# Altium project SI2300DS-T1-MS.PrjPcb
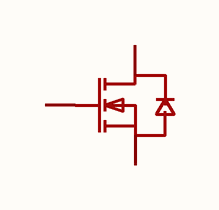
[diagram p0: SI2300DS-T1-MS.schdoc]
1 sheet, 1 parts. Net scope: global (net labels, ports and power ports of the same name join across sheets).

## Sheet SI2300DS-T1-MS.schdoc
size 127 x 101 mm

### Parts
Q?  si2300ds-t1-ms  [SOT-23-3_L2.9-W1.6-P1.90-LS2.8-BR]  (value not drawn)

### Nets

Not connected (* = marked no-connect by the designer): Q? 1(G) 2(S) 3(D)

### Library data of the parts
Q? = si2300ds-t1-ms: 数量:1个N沟道;漏源电压(Vdss):20V;连续漏极电流(Id):6A;导通电阻(RDS(on)):27mΩ@4.5V;耗散功率(Pd):1.25W;阈值电压(Vgs(th)):650mV;; Manufacturer: MSKSEMI(美森科); AddInBom: yes; ModelId: 89cb27a44ab2466697082bb9fd73a7d0; ModelName: SOT-23-3L_L2.9-W1.6-H1.1-LS2.8-P0.95; ModelTransform: 114.173,110.236,0,90,0,0,0,0,0; Number: 1个N沟道; Drain to Source Voltage: 20V; Current - Continuous Drain(Id): 6A; Pd - Power Dissipation: 1.25W; Gate Threshold Voltage (Vgs(th)): 650mV; Gate Charge(Qg): 15nC@4.5V; Input Capacitance(Ciss): 500pF; Reverse Transfer Capacitance (Crss@Vds): 96pF; Type: N沟道; Output Capacitance(Coss): 295pF; Vgs: ±12V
